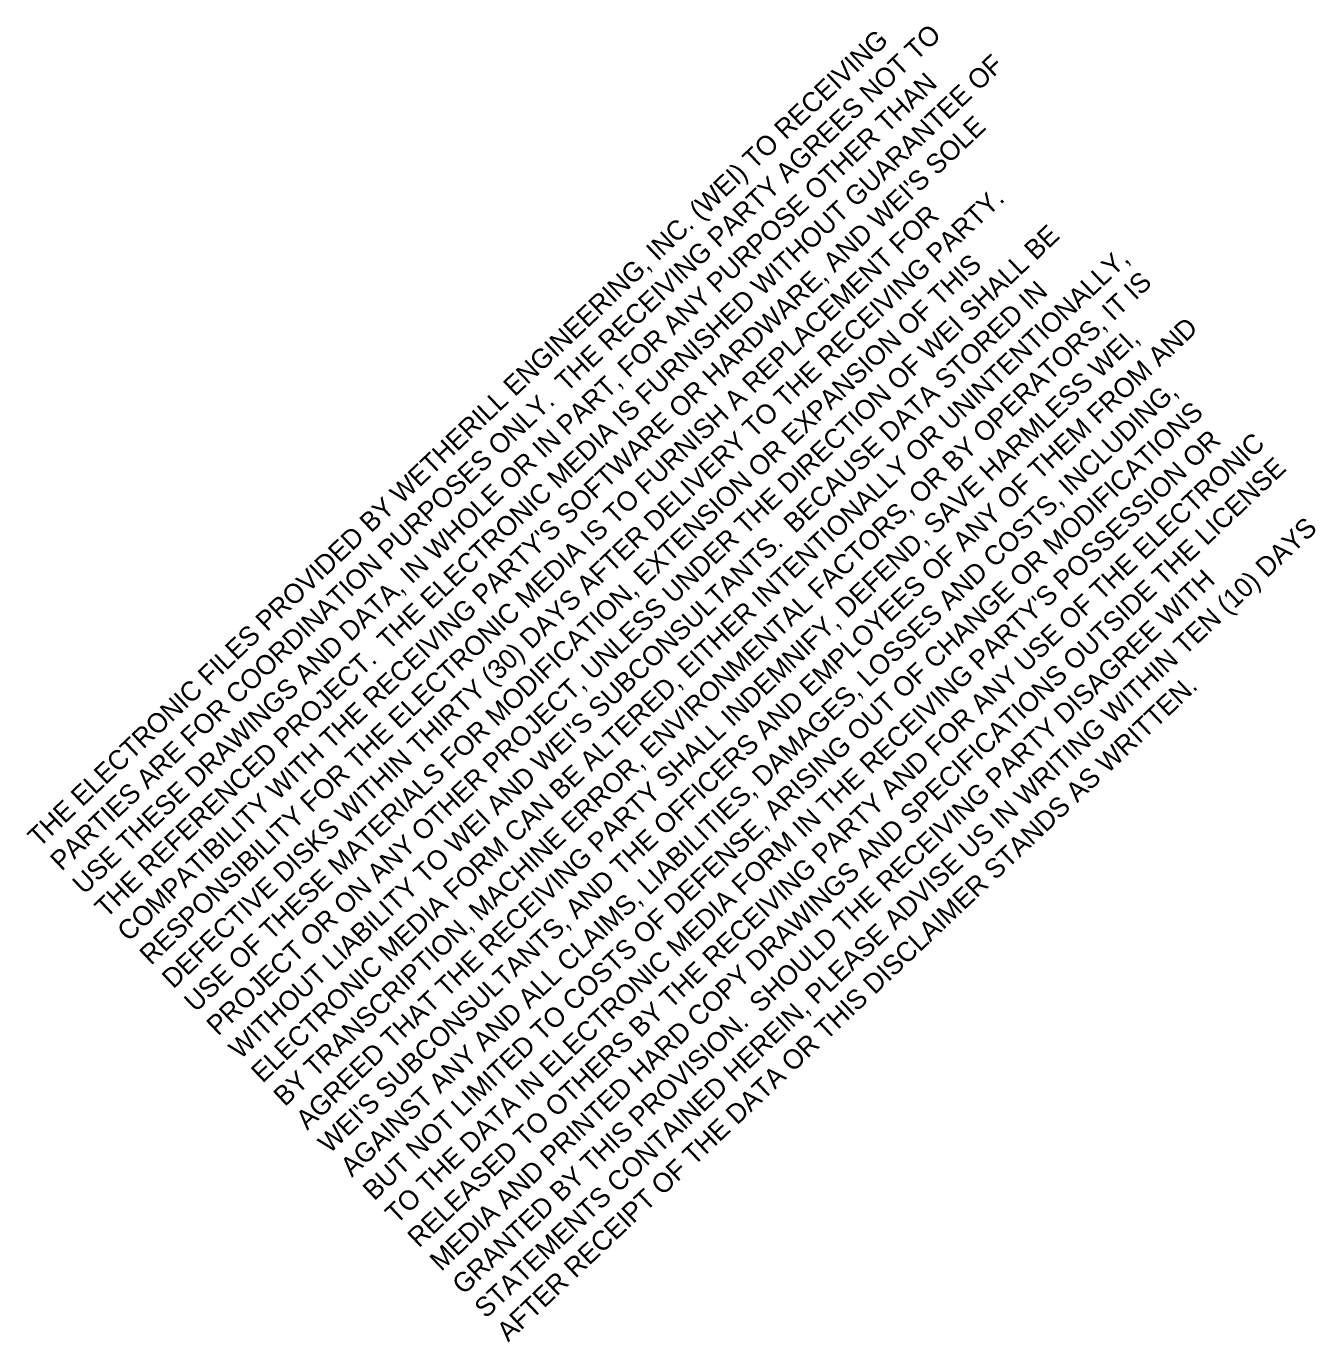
# Model space of a CAD drawing. Extents: x 2143899 to 2147907, y 717411 to 721359.
# Drawn here: x 2146401 to 2147907, y 719822 to 721359 of the extents above; entities that cross this region are included whole.
import ezdxf

# ---------------------------------------------------------------- set-up
doc = ezdxf.new("R2010")
doc.units = 0
doc.layers.add('Default', color=7, linetype='Continuous')

msp = doc.modelspace()

# ---------------------------------------------------------------- texts
at = {"layer": 'Default'}
for s, p in [('THE ELECTRONIC FILES PROVIDED BY WETHERILL ENGINEERING, INC. (WEI) TO RECEIVING ', (2146416.4, 720399.5)), ('PARTIES ARE FOR COORDINATION PURPOSES ONLY.  THE RECEIVING PARTY AGREES NOT TO ', (2146442.5, 720372)), ('THE REFERENCED PROJECT.  THE ELECTRONIC MEDIA IS FURNISHED WITHOUT GUARANTEE OF ', (2146494.6, 720317)), ('USE THESE DRAWINGS AND DATA, IN WHOLE OR IN PART, FOR ANY PURPOSE OTHER THAN ', (2146468.6, 720344.5)), ("COMPATIBILITY WITH THE RECEIVING PARTY'S SOFTWARE OR HARDWARE, AND WEI'S SOLE ", (2146520.7, 720289.5)), ('DEFECTIVE DISKS WITHIN THIRTY (30) DAYS AFTER DELIVERY TO THE RECEIVING PARTY.  ', (2146572.9, 720234.6)), ('RESPONSIBILITY FOR THE ELECTRONIC MEDIA IS TO FURNISH A REPLACEMENT FOR ', (2146546.8, 720262.1)), ('PROJECT OR ON ANY OTHER PROJECT, UNLESS UNDER THE DIRECTION OF WEI SHALL BE ', (2146625, 720179.6)), ('USE OF THESE MATERIALS FOR MODIFICATION, EXTENSION OR EXPANSION OF THIS ', (2146598.9, 720207.1)), ('ELECTRONIC MEDIA FORM CAN BE ALTERED, EITHER INTENTIONALLY OR UNINTENTIONALLY, ', (2146677.1, 720124.6)), ('BY TRANSCRIPTION, MACHINE ERROR, ENVIRONMENTAL FACTORS, OR BY OPERATORS, IT IS ', (2146703.2, 720097.1)), ("WITHOUT LIABILITY TO WEI AND WEI'S SUBCONSULTANTS.  BECAUSE DATA STORED IN ", (2146651.1, 720152.1)), ("WEI'S SUBCONSULTANTS, AND THE OFFICERS AND EMPLOYEES OF ANY OF THEM FROM AND ", (2146755.3, 720042.1)), ('AGREED THAT THE RECEIVING PARTY SHALL INDEMNIFY, DEFEND, SAVE HARMLESS WEI, ', (2146729.3, 720069.6)), ('AGAINST ANY AND ALL CLAIMS, LIABILITIES, DAMAGES, LOSSES AND COSTS, INCLUDING, ', (2146781.4, 720014.6)), ('BUT NOT LIMITED TO COSTS OF DEFENSE, ARISING OUT OF CHANGE OR MODIFICATIONS ', (2146807.5, 719987.1)), ("TO THE DATA IN ELECTRONIC MEDIA FORM IN THE RECEIVING PARTY'S POSSESSION OR ", (2146833.6, 719959.6)), ('RELEASED TO OTHERS BY THE RECEIVING PARTY AND FOR ANY USE OF THE ELECTRONIC ', (2146859.6, 719932.1)), ('MEDIA AND PRINTED HARD COPY DRAWINGS AND SPECIFICATIONS OUTSIDE THE LICENSE ', (2146885.7, 719904.7)), ('STATEMENTS CONTAINED HEREIN, PLEASE ADVISE US IN WRITING WITHIN TEN (10) DAYS ', (2146937.8, 719849.7)), ('GRANTED BY THIS PROVISION.  SHOULD THE RECEIVING PARTY DISAGREE WITH ', (2146911.8, 719877.2)), ('AFTER RECEIPT OF THE DATA OR THIS DISCLAIMER STANDS AS WRITTEN.', (2146963.9, 719822.2))]:
    msp.add_text(s, height=22.733, rotation=43.479, dxfattribs=at).set_placement(p)

doc.saveas('drawing.dxf')
